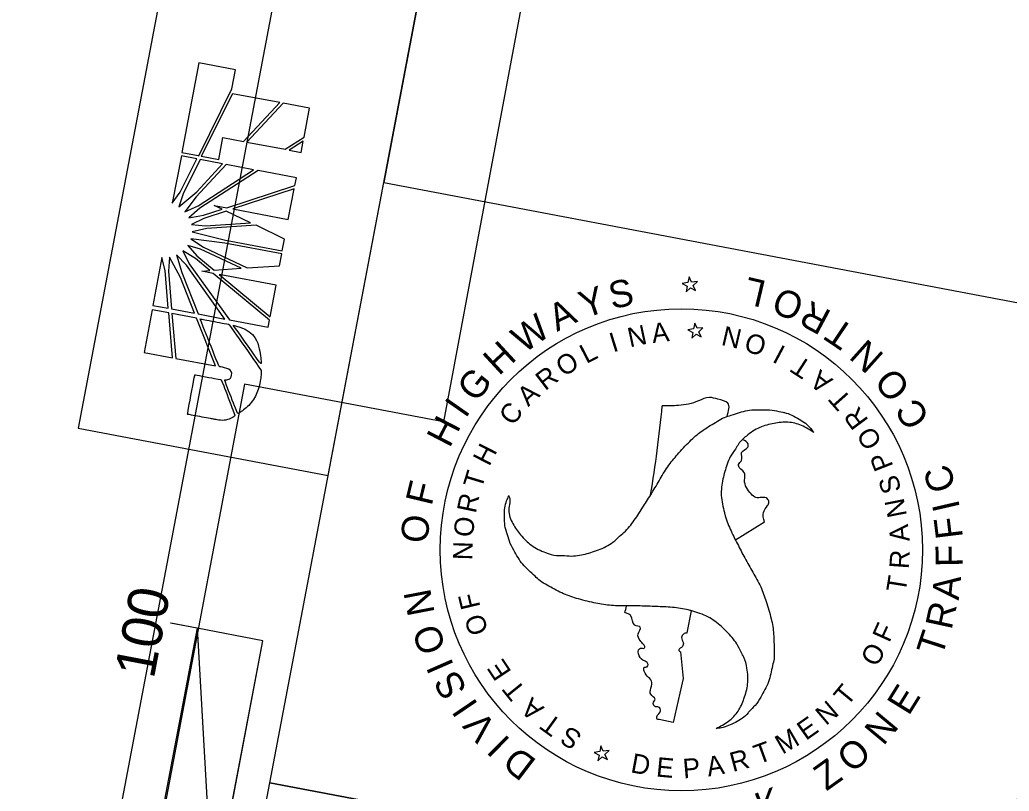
# Model space of a CAD drawing. Extents: x 1615680 to 1619687, y 899305 to 902270.
# Drawn here: x 1616793.9 to 1616978.5, y 900619.3 to 900763.2 of the extents above; entities that cross this region are included whole.
import ezdxf

# ---------------------------------------------------------------- set-up
doc = ezdxf.new("R2010")
doc.units = 0
for name, color, linetype in [('Default', 7, 'Continuous'), ('DEV PSS CELL', 7, 'Continuous'), ('PCB (Plan View)', 7, 'Continuous'), ('Prop Conc 4in Sidewalk', 7, 'Continuous'), ('Prop Mkg Solid Yel Skip RT Rpm 80ft', 7, 'Continuous'), ('Scratch_Level_3', 7, 'Continuous'), ('Scratch_Level_7', 7, 'Continuous'), ('Scratch_Level_8', 7, 'Continuous'), ('Stage 2', 7, 'Continuous')]:
    doc.layers.add(name, color=color, linetype=linetype)

msp = doc.modelspace()

# ---------------------------------------------------------------- linework, layer by layer
at = {"layer": 'Default'}
for p, q in [((1616827.31, 900755.17), (1616824.15, 900738.45)), ((1616834.16, 900753.88), (1616827.31, 900755.17)), ((1616833.49, 900750.32), (1616834.16, 900753.88)), ((1616827.31, 900737.85), (1616833.49, 900750.32)), ((1616833.63, 900749.42), (1616827.78, 900737.76)), ((1616842.41, 900747.76), (1616833.63, 900749.42)), ((1616835.63, 900740.51), (1616842.41, 900747.76)), ((1616843.03, 900747.65), (1616836.29, 900740.38)), ((1616847.97, 900746.71), (1616843.03, 900747.65)), ((1616846.95, 900741.32), (1616847.97, 900746.71)), ((1616831.04, 900737.15), (1616831.81, 900741.23)), ((1616831.81, 900741.23), (1616835.63, 900740.51)), ((1616843.4, 900739.04), (1616846.95, 900741.32)), ((1616846.8, 900740.53), (1616844.18, 900738.89)), ((1616846.41, 900738.47), (1616846.8, 900740.53)), ((1616836.29, 900740.38), (1616843.4, 900739.04)), ((1616844.18, 900738.89), (1616846.41, 900738.47)), ((1616824.07, 900737.82), (1616822.36, 900729.01)), ((1616823.84, 900731.04), (1616826.93, 900737.28)), ((1616826.93, 900737.28), (1616824.07, 900737.82)), ((1616824.15, 900738.45), (1616827.22, 900737.87)), ((1616827.54, 900737.17), (1616824.37, 900730.71)), ((1616827.22, 900737.87), (1616827.31, 900737.85)), ((1616831.74, 900736.32), (1616827.54, 900737.17)), ((1616827.78, 900737.76), (1616827.84, 900737.75)), ((1616827.84, 900737.75), (1616831.04, 900737.15)), ((1616832.45, 900736.19), (1616826.81, 900730.17)), ((1616826.95, 900731.13), (1616831.74, 900736.32)), ((1616827.18, 900728.51), (1616837.54, 900735.22)), ((1616838.37, 900735.07), (1616827.5, 900728.08)), ((1616837.54, 900735.22), (1616832.45, 900736.19)), ((1616845.51, 900733.72), (1616838.37, 900735.07)), ((1616845.25, 900732.31), (1616845.51, 900733.72)), ((1616832.52, 900728.14), (1616845.25, 900732.31)), ((1616845.08, 900731.66), (1616833.66, 900727.92)), ((1616844.01, 900725.97), (1616845.08, 900731.66)), ((1616822.36, 900729.01), (1616823.84, 900731.04)), ((1616823.59, 900728.31), (1616826.95, 900731.13)), ((1616824.37, 900730.71), (1616823.59, 900728.31)), ((1616826.81, 900730.17), (1616824.69, 900727.39)), ((1616824.69, 900727.39), (1616827.18, 900728.51)), ((1616827.5, 900728.08), (1616825.48, 900726.27)), ((1616828.21, 900726.76), (1616831.69, 900727.87)), ((1616831.69, 900727.87), (1616830.19, 900728.58)), ((1616830.19, 900728.58), (1616832.52, 900728.14)), ((1616833.66, 900727.92), (1616844.01, 900725.97)), ((1616825.48, 900726.27), (1616828.21, 900726.76)), ((1616828.28, 900726.16), (1616825.97, 900725.01)), ((1616832.4, 900727.52), (1616828.28, 900726.16)), ((1616836.99, 900725.33), (1616832.4, 900727.52)), ((1616825.97, 900725.01), (1616828.57, 900724.79)), ((1616828.83, 900724.24), (1616826.09, 900723.67)), ((1616828.57, 900724.79), (1616836.99, 900725.33)), ((1616837.99, 900724.87), (1616828.83, 900724.24)), ((1616843.31, 900722.28), (1616837.99, 900724.87)), ((1616832.18, 900721.51), (1616825.84, 900722.36)), ((1616825.84, 900722.36), (1616828.18, 900720.79)), ((1616826.09, 900723.67), (1616832.28, 900722.08)), ((1616832.28, 900722.08), (1616842.89, 900720.07)), ((1616842.89, 900720.07), (1616843.31, 900722.28)), ((1616825.24, 900721.11), (1616826.96, 900719.15)), ((1616827.65, 900720.42), (1616825.24, 900721.11)), ((1616835.2, 900716.86), (1616827.65, 900720.42)), ((1616828.18, 900720.79), (1616836.35, 900716.92)), ((1616842.79, 900719.51), (1616832.18, 900721.51)), ((1616820.45, 900718.87), (1616818.76, 900709.92)), ((1616821.03, 900716.4), (1616820.45, 900718.87)), ((1616821.82, 900718.94), (1616821.64, 900716.28)), ((1616823.88, 900715.14), (1616821.82, 900718.94)), ((1616825.04, 900717.42), (1616823.18, 900719.36)), ((1616823.18, 900719.36), (1616824.14, 900716.04)), ((1616824.31, 900720.1), (1616825.54, 900717.68)), ((1616826.67, 900718.65), (1616824.31, 900720.1)), ((1616829.39, 900716.41), (1616826.67, 900718.65)), ((1616826.96, 900719.15), (1616830.18, 900716.49)), ((1616842.37, 900717.33), (1616842.79, 900719.51)), ((1616832.19, 900707.38), (1616825.04, 900717.42)), ((1616825.54, 900717.68), (1616833.03, 900707.22)), ((1616830.18, 900716.49), (1616835.2, 900716.86)), ((1616836.35, 900716.92), (1616842.37, 900717.33)), ((1616821.61, 900709.38), (1616821.03, 900716.4)), ((1616821.64, 900716.28), (1616822.22, 900709.27)), ((1616826.53, 900708.45), (1616823.88, 900715.14)), ((1616824.14, 900716.04), (1616827.22, 900708.32)), ((1616827.87, 900716.29), (1616829.39, 900716.41)), ((1616829.97, 900715.89), (1616827.87, 900716.29)), ((1616840.5, 900707.17), (1616829.97, 900715.89)), ((1616841.73, 900713.72), (1616831.12, 900715.68)), ((1616831.12, 900715.68), (1616840.61, 900707.79)), ((1616840.61, 900707.79), (1616841.73, 900713.72)), ((1616818.76, 900709.92), (1616821.61, 900709.38)), ((1616822.22, 900709.27), (1616826.53, 900708.45)), ((1616818.64, 900709.09), (1616817.14, 900701.13)), ((1616821.71, 900708.51), (1616818.64, 900709.09)), ((1616822.41, 900700.13), (1616821.71, 900708.51)), ((1616826.9, 900707.53), (1616822.29, 900708.4)), ((1616822.29, 900708.4), (1616823.02, 900700.02)), ((1616830.44, 900698.62), (1616826.9, 900707.53)), ((1616827.22, 900708.32), (1616832.19, 900707.38)), ((1616833.03, 900707.22), (1616840.25, 900705.86)), ((1616840.25, 900705.86), (1616840.5, 900707.17)), ((1616817.14, 900701.13), (1616822.41, 900700.13)), ((1616823.02, 900700.02), (1616830.44, 900698.62))]:
    msp.add_line(p, q, dxfattribs=at)
for points in [[(1616827.78, 900737.76), (1616827.84, 900737.75), (1616831.04, 900737.15), (1616831.81, 900741.23), (1616835.63, 900740.51), (1616842.41, 900747.76), (1616833.63, 900749.42), (1616827.78, 900737.76)], [(1616836.29, 900740.38), (1616843.4, 900739.04), (1616846.95, 900741.32), (1616847.97, 900746.71), (1616843.03, 900747.65), (1616836.29, 900740.38), (1616836.29, 900740.38)], [(1616846.41, 900738.47), (1616846.41, 900738.47), (1616846.8, 900740.53), (1616844.18, 900738.89), (1616846.41, 900738.47)], [(1616823.84, 900731.04), (1616826.93, 900737.28), (1616824.07, 900737.82), (1616822.36, 900729.01), (1616823.84, 900731.04)], [(1616823.59, 900728.31), (1616826.95, 900731.13), (1616831.74, 900736.32), (1616827.54, 900737.17), (1616824.37, 900730.71), (1616823.59, 900728.31)], [(1616824.69, 900727.39), (1616827.18, 900728.51), (1616837.54, 900735.22), (1616832.45, 900736.19), (1616826.81, 900730.17), (1616824.69, 900727.39)], [(1616825.48, 900726.27), (1616828.21, 900726.76), (1616831.69, 900727.87), (1616830.19, 900728.58), (1616832.52, 900728.14), (1616845.25, 900732.31), (1616845.51, 900733.72), (1616838.37, 900735.07), (1616827.5, 900728.08), (1616825.48, 900726.27)], [(1616844.01, 900725.97), (1616845.08, 900731.66), (1616833.66, 900727.92), (1616844.01, 900725.97)], [(1616825.97, 900725.01), (1616828.57, 900724.79), (1616836.99, 900725.33), (1616832.4, 900727.52), (1616828.28, 900726.16), (1616825.97, 900725.01)], [(1616826.09, 900723.67), (1616832.28, 900722.08), (1616842.89, 900720.07), (1616843.31, 900722.28), (1616837.99, 900724.87), (1616828.83, 900724.24), (1616826.09, 900723.67)], [(1616828.18, 900720.79), (1616836.35, 900716.92), (1616842.37, 900717.33), (1616842.79, 900719.51), (1616832.18, 900721.51), (1616825.84, 900722.36), (1616828.18, 900720.79)], [(1616825.24, 900721.11), (1616826.96, 900719.15), (1616830.18, 900716.49), (1616835.2, 900716.86), (1616827.65, 900720.42), (1616825.24, 900721.11)], [(1616821.03, 900716.4), (1616820.45, 900718.87), (1616818.76, 900709.92), (1616821.61, 900709.38), (1616821.03, 900716.4)], [(1616822.22, 900709.27), (1616826.53, 900708.45), (1616823.88, 900715.14), (1616821.82, 900718.94), (1616821.64, 900716.28), (1616822.22, 900709.27)], [(1616827.22, 900708.32), (1616832.19, 900707.38), (1616825.04, 900717.42), (1616823.18, 900719.36), (1616824.14, 900716.04), (1616827.22, 900708.32)], [(1616824.31, 900720.1), (1616825.54, 900717.68), (1616833.03, 900707.22), (1616840.25, 900705.86), (1616840.5, 900707.17), (1616829.97, 900715.89), (1616827.87, 900716.29), (1616829.39, 900716.41), (1616826.67, 900718.65), (1616824.31, 900720.1)], [(1616840.61, 900707.79), (1616841.73, 900713.72), (1616831.12, 900715.68), (1616840.61, 900707.79)], [(1616822.41, 900700.13), (1616821.71, 900708.51), (1616818.64, 900709.09), (1616817.14, 900701.13), (1616822.41, 900700.13)], [(1616830.44, 900698.62), (1616826.9, 900707.53), (1616822.29, 900708.4), (1616823.02, 900700.02), (1616830.44, 900698.62)]]:
    msp.add_lwpolyline(points, dxfattribs=at)
for points in [[(1616833.44, 900696.87), (1616833.35, 900696.4), (1616833.01, 900696.04), (1616832.1, 900696.03), (1616832.1, 900696.03), (1616834.55, 900689.66), (1616834.55, 900689.66), (1616836.73, 900691.07), (1616838.37, 900693.67), (1616838.81, 900696.04), (1616838.93, 900696.66), (1616838.97, 900697.14), (1616838.96, 900697.82), (1616838.96, 900697.82), (1616832.91, 900706.39), (1616832.91, 900706.39), (1616832.91, 900706.39), (1616827.55, 900707.4), (1616827.55, 900707.4), (1616827.55, 900707.4), (1616831.11, 900698.49), (1616831.11, 900698.49), (1616833.11, 900698.11), (1616833.56, 900697.52), (1616833.44, 900696.87)], [(1616833.44, 900696.87), (1616833.35, 900696.4), (1616833.01, 900696.04), (1616832.1, 900696.03), (1616832.1, 900696.03), (1616834.55, 900689.66), (1616834.55, 900689.66), (1616836.73, 900691.07), (1616838.37, 900693.67), (1616838.81, 900696.04), (1616838.93, 900696.66), (1616838.97, 900697.14), (1616838.96, 900697.82), (1616838.96, 900697.82), (1616832.91, 900706.39), (1616832.91, 900706.39), (1616832.91, 900706.39), (1616827.55, 900707.4), (1616827.55, 900707.4), (1616827.55, 900707.4), (1616831.11, 900698.49), (1616831.11, 900698.49), (1616833.11, 900698.11), (1616833.56, 900697.52), (1616833.44, 900696.87)], [(1616833.75, 900706.23), (1616833.75, 900706.23), (1616838.97, 900698.83), (1616838.97, 900698.83), (1616838.8, 900702), (1616837.36, 900705.4), (1616833.75, 900706.23)], [(1616833.75, 900706.23), (1616833.75, 900706.23), (1616838.97, 900698.83), (1616838.97, 900698.83), (1616838.8, 900702), (1616837.36, 900705.4), (1616833.75, 900706.23)], [(1616826.59, 900696.98), (1616826.59, 900696.98), (1616825.2, 900689.61), (1616825.2, 900689.61), (1616825.2, 900689.61), (1616829.81, 900688.74), (1616829.81, 900688.74), (1616829.81, 900688.74), (1616830.29, 900688.65), (1616830.29, 900688.65), (1616831.74, 900688.38), (1616832.97, 900688.64), (1616834.09, 900689.29), (1616834.09, 900689.29), (1616831.55, 900696.04), (1616831.46, 900696.06), (1616831.46, 900696.06), (1616826.59, 900696.98), (1616826.59, 900696.98)], [(1616826.59, 900696.98), (1616826.59, 900696.98), (1616825.2, 900689.61), (1616825.2, 900689.61), (1616825.2, 900689.61), (1616829.81, 900688.74), (1616829.81, 900688.74), (1616829.81, 900688.74), (1616830.29, 900688.65), (1616830.29, 900688.65), (1616831.74, 900688.38), (1616832.97, 900688.64), (1616834.09, 900689.29), (1616834.09, 900689.29), (1616831.55, 900696.04), (1616831.46, 900696.06), (1616831.46, 900696.06), (1616826.59, 900696.98), (1616826.59, 900696.98)]]:
    msp.add_open_spline(points, degree=3, dxfattribs=at)
at = {"layer": 'DEV PSS CELL'}
msp.add_lwpolyline([(1616859.19, 900973.59), (1616804.79, 900687.04), (1616851.47, 900678.18), (1616905.88, 900964.73)], close=True, dxfattribs=at)
at = {"layer": 'PCB (Plan View)'}
for p, q in [((1616826.98, 900649.69), (1616822.07, 900650.62)), ((1616826.98, 900649.69), (1616799.02, 900502.32)), ((1616839.28, 900647.36), (1616826.98, 900649.69)), ((1616811.3, 900499.99), (1616839.28, 900647.36))]:
    msp.add_line(p, q, dxfattribs=at)
msp.add_lwpolyline([(1616826.98, 900649.69), (1616829.94, 900598.24), (1616839.28, 900647.36)], close=True, dxfattribs=at)
at = {"layer": 'Prop Conc 4in Sidewalk'}
msp.add_lwpolyline([(1616176.29, 901060.7), (1616848.46, 900914.27), (1616896.28, 900812.91), (1616872.94, 900688.21), (1616835.87, 900695.21), (1616753.94, 900262.18), (1616898.09, 900233.43), (1616734.79, 899562.1), (1616202.98, 899609.43), (1616198.71, 899647.14), (1615822.69, 899825.07), (1616054.34, 901080.76)], close=True, dxfattribs=at)
at = {"layer": 'Prop Mkg Solid Yel Skip RT Rpm 80ft'}
msp.add_circle((1616917.34, 900664.32), 44.97, dxfattribs=at)
at = {"layer": 'Scratch_Level_3'}
for p, q in [((1616918.77, 900715.25), (1616918.56, 900714.19)), ((1616919.23, 900714.26), (1616918.77, 900715.25)), ((1616918.56, 900714.19), (1616917.51, 900714.02)), ((1616917.51, 900714.02), (1616918.44, 900713.51)), ((1616918.44, 900713.51), (1616918.23, 900712.45)), ((1616918.23, 900712.45), (1616919.03, 900713.2)), ((1616919.03, 900713.2), (1616920, 900712.69)), ((1616920.32, 900714.39), (1616919.23, 900714.26)), ((1616919.52, 900713.63), (1616920.32, 900714.39)), ((1616920, 900712.69), (1616919.52, 900713.63)), ((1616919.62, 900705.56), (1616918.56, 900705.39)), ((1616919.82, 900706.62), (1616919.62, 900705.56)), ((1616920.28, 900705.64), (1616919.82, 900706.62)), ((1616921.37, 900705.76), (1616920.28, 900705.64)), ((1616920.58, 900705.01), (1616921.37, 900705.76)), ((1616918.56, 900705.39), (1616919.49, 900704.89)), ((1616919.49, 900704.89), (1616919.29, 900703.83)), ((1616919.29, 900703.83), (1616920.08, 900704.57)), ((1616920.08, 900704.57), (1616921.05, 900704.06)), ((1616921.05, 900704.06), (1616920.58, 900705.01)), ((1616927.43, 900666.17), (1616932.82, 900669.53)), ((1616918.41, 900648.8), (1616919.23, 900652.93)), ((1616917.17, 900645.27), (1616917.66, 900640.28)), ((1616917.66, 900640.28), (1616915.79, 900632.1)), ((1616915.79, 900632.1), (1616913.19, 900632.68)), ((1616902.1, 900626.67), (1616901.05, 900626.51)), ((1616901.05, 900626.51), (1616901.98, 900626)), ((1616902.31, 900627.74), (1616902.1, 900626.67)), ((1616902.77, 900626.75), (1616902.31, 900627.74)), ((1616903.86, 900626.87), (1616902.77, 900626.75)), ((1616903.06, 900626.12), (1616903.86, 900626.87)), ((1616903.54, 900625.18), (1616903.06, 900626.12)), ((1616901.98, 900626), (1616901.78, 900624.94)), ((1616901.78, 900624.94), (1616902.57, 900625.69)), ((1616902.57, 900625.69), (1616903.54, 900625.18))]:
    msp.add_line(p, q, dxfattribs=at)
for start, end in [(350.4529, 354.5729), (344.9279, 345.2256)]:
    msp.add_arc((1616681.63, 900713.24), 233.19, start, end, dxfattribs=at)
for points in [[(1616925.85, 900689.2), (1616926.01, 900691.68), (1616924.16, 900692.4), (1616922.56, 900692.74), (1616920.51, 900692.09), (1616916.81, 900691.24), (1616913.77, 900691.18)], [(1616885.09, 900674.44), (1616885.15, 900674.35), (1616885.14, 900671.73), (1616885.9, 900669.21), (1616887.35, 900667.1), (1616889.36, 900665.16), (1616892, 900663.79), (1616894.06, 900663.26), (1616895.09, 900663.25), (1616896.88, 900663.16), (1616898.33, 900663.29), (1616901.12, 900664.05), (1616903.92, 900665.29), (1616906.42, 900667.39), (1616906.62, 900667.57), (1616908.56, 900669.82), (1616910.25, 900672.43), (1616911.82, 900674.91), (1616913.38, 900677.54), (1616915.02, 900680.12), (1616916.87, 900682.4), (1616919.19, 900684.83), (1616921.43, 900686.67), (1616924.06, 900688.3), (1616925.37, 900689.03), (1616926.65, 900689.42), (1616929.69, 900690.32), (1616932.83, 900690.43), (1616934.72, 900690.32), (1616936.29, 900689.97), (1616936.55, 900689.92), (1616939.3, 900688.71), (1616941.48, 900686.96), (1616942.02, 900686.2)], [(1616942.02, 900686.2), (1616939.76, 900687.51), (1616937.22, 900688.12), (1616934.64, 900687.9), (1616931.95, 900687.13), (1616929.47, 900685.55), (1616927.98, 900684.03), (1616927.45, 900683.12), (1616926.46, 900681.67), (1616925.87, 900680.28), (1616925.1, 900677.53), (1616924.79, 900674.45), (1616925.36, 900671.25), (1616925.42, 900670.99), (1616926.44, 900668.18), (1616927.8, 900665.43), (1616929.16, 900662.79), (1616930.68, 900660.13), (1616932.13, 900657.42), (1616933.14, 900654.69), (1616934.09, 900651.45), (1616934.55, 900648.6), (1616934.65, 900645.52), (1616934.64, 900643.99), (1616934.34, 900642.71), (1616933.59, 900639.66), (1616932.13, 900636.85), (1616931.1, 900635.29), (1616929.97, 900634.12), (1616929.8, 900633.9), (1616927.41, 900632.12), (1616924.81, 900631.11), (1616923.83, 900630.99)], [(1616932.82, 900669.53), (1616932.64, 900671.29), (1616933.43, 900672.58), (1616933.66, 900673.23), (1616933.35, 900673.86), (1616931.24, 900674.09), (1616930.36, 900674.75), (1616929.12, 900677.31), (1616929.08, 900678.76), (1616927.99, 900680.03), (1616928.1, 900680.44), (1616928.58, 900681.01), (1616928.57, 900682.48), (1616929.71, 900683.44), (1616929.78, 900684.12), (1616928.83, 900684.85)], [(1616923.83, 900630.99), (1616926.14, 900632.33), (1616927.91, 900634.21), (1616929.01, 900636.54), (1616929.7, 900639.28), (1616929.57, 900642.22), (1616928.98, 900644.28), (1616928.5, 900645.19), (1616927.68, 900646.76), (1616926.81, 900647.94), (1616924.8, 900650.02), (1616922.29, 900651.8), (1616919.26, 900652.93), (1616919, 900653), (1616916.04, 900653.54), (1616912.98, 900653.71), (1616910.03, 900653.83), (1616906.95, 900653.87), (1616903.91, 900653.96), (1616901.02, 900654.45), (1616897.76, 900655.26), (1616895.03, 900656.27), (1616892.3, 900657.74), (1616891.02, 900658.51), (1616890.04, 900659.4), (1616887.76, 900661.61), (1616886.08, 900664.25), (1616885.25, 900665.94), (1616884.78, 900667.48), (1616884.69, 900667.74), (1616884.32, 900670.71), (1616884.74, 900673.47), (1616885.15, 900674.35)], [(1616913.19, 900632.68), (1616912.93, 900632.64), (1616912.74, 900633.14), (1616913.47, 900634.27), (1616913.06, 900634.98), (1616912.52, 900635.05), (1616912.09, 900635.65), (1616912.42, 900636.45), (1616911.61, 900637.38), (1616911.55, 900638.11), (1616911.83, 900639.58), (1616910.41, 900641.66), (1616910.44, 900642.4), (1616910.95, 900642.51), (1616911.12, 900642.94), (1616909.82, 900643.99), (1616909.66, 900644.22), (1616909.36, 900645.66), (1616909.71, 900645.97), (1616910.37, 900645.96), (1616910.51, 900646.13), (1616910.29, 900646.63), (1616909.63, 900647.39), (1616909.26, 900648.61), (1616909.67, 900649.86), (1616908.65, 900650.28), (1616907.94, 900651.97), (1616907.39, 900652.39), (1616906.79, 900652.59)], [(1616918.41, 900648.8), (1616917.71, 900648.59), (1616917.39, 900647.96), (1616917.69, 900646.95), (1616917.54, 900646.29), (1616916.84, 900645.65), (1616917.17, 900645.27)]]:
    msp.add_spline(points, degree=3, dxfattribs=at)
at = {"layer": 'Scratch_Level_7'}
for points in [[(1616905.88, 900964.73), (1616861.86, 900732.87), (1616996.95, 900707.23), (1617040.97, 900939.08)], [(1616840.59, 900620.87), (1616861.86, 900732.87), (1616996.95, 900707.23), (1616975.68, 900595.22)], [(1616803.28, 900424.35), (1616840.59, 900620.87), (1616975.68, 900595.22), (1616938.37, 900398.7)]]:
    msp.add_lwpolyline(points, close=True, dxfattribs=at)
at = {"layer": 'Scratch_Level_8'}
msp.add_lwpolyline([(1616054.34, 901080.76), (1615793.19, 899705.33), (1616726.52, 899528.12), (1616890.46, 900391.55), (1616774.26, 900413.61), (1616871.48, 900925.61)], close=True, dxfattribs=at)
at = {"layer": 'Stage 2'}
msp.add_line((1616826.99, 900649.7), (1616822.06, 900650.64), dxfattribs=at)

# ---------------------------------------------------------------- texts
at = {"layer": 'PCB (Plan View)'}
msp.add_text('100', height=7.5, rotation=79.2541, dxfattribs=at).set_placement((1616818.91, 900640.06))
at = {"layer": 'Prop Mkg Solid Yel Skip RT Rpm 80ft'}
for s, height, rotation, p in [('L', 5.04, 166.6784, (1616933.41, 900714.4)), ('O', 5.04, 158.239, (1616940.59, 900711.5)), ('R', 5.04, 152.0012, (1616945.58, 900708.69)), ('T', 5.04, 146.1304, (1616949.97, 900705.57)), ('N', 5.04, 138.1413, (1616955.38, 900700.64)), ('O', 5.04, 129.702, (1616960.3, 900694.66)), ('C', 5.04, 122.3301, (1616963.84, 900688.9)), ('C', 5.04, 107.2527, (1616968.63, 900675.95)), ('T', 3.63, 73.0378, (1616880.06, 900675.5)), ('I', 5.04, 102.9996, (1616969.35, 900672.12)), ('F', 5.04, 97.012, (1616969.88, 900666.65)), ('F', 5.04, 91.0244, (1616969.84, 900661.16)), ('A', 5.04, 84.0528, (1616969.07, 900654.81)), ('R', 5.04, 77.815, (1616967.73, 900649.24)), ('T', 5.04, 71.9442, (1616965.92, 900644.17)), ('E', 5.04, 58.201, (1616959.74, 900633.2)), ('N', 5.04, 50.212, (1616955.01, 900627.61)), ('O', 5.04, 41.7727, (1616949.21, 900622.48)), ('Z', 5.04, 35.4181, (1616944.38, 900619.21)), ('K', 5.04, 21.0412, (1616932.34, 900613.91))]:
    msp.add_text(s, height=height, rotation=rotation, dxfattribs=at).set_placement(p)
at = {"layer": 'Scratch_Level_3'}
for s, height, rotation, p in [('S', 5.04, 12.4743, (1616904.4, 900709.18)), ('Y', 5.04, 18.9977, (1616899.33, 900707.45)), ('A', 5.04, 26.0256, (1616894.13, 900704.96)), ('W', 5.04, 35.0626, (1616887.96, 900700.86)), ('N', 3.63, 12.1007, (1616907.73, 900702.07)), ('A', 3.63, 7.0227, (1616912.01, 900702.88)), ('N', 3.63, 166.9823, (1616928.85, 900705.33)), ('I', 3.63, 17.1788, (1616904.59, 900701.12)), ('O', 3.63, 162.1763, (1616933.52, 900703.81)), ('H', 5.04, 42.7126, (1616883.29, 900696.66)), ('L', 3.63, 27.335, (1616899.6, 900698.96)), ('I', 3.63, 152.0201, (1616937.01, 900702.05)), ('O', 3.63, 32.4131, (1616895.39, 900696.49)), ('T', 3.63, 146.942, (1616941.93, 900699.08)), ('R', 3.63, 37.4912, (1616891.93, 900693.88)), ('A', 3.63, 141.8639, (1616945.78, 900696.08)), ('G', 5.04, 50.7661, (1616879.02, 900691.62)), ('A', 3.63, 42.5693, (1616888.77, 900690.92)), ('I', 5.04, 55.0534, (1616877.05, 900688.7)), ('T', 3.63, 131.7077, (1616949.3, 900692.41)), ('C', 3.63, 52.7254, (1616885.92, 900687.29)), ('R', 3.63, 126.6297, (1616952.37, 900688.51)), ('H', 5.04, 62.7034, (1616874.1, 900683.16)), ('O', 3.63, 121.5516, (1616954.91, 900684.44)), ('H', 3.63, 62.8816, (1616881.51, 900679.75)), ('P', 3.63, 111.3954, (1616956.93, 900679.91)), ('S', 3.63, 106.3173, (1616958.42, 900675.42)), ('F', 5.04, 76.5069, (1616870.74, 900672.37)), ('R', 3.63, 78.1158, (1616878.97, 900670.99)), ('N', 3.63, 101.2392, (1616959.44, 900670.73)), ('O', 5.04, 85.0143, (1616869.99, 900665.43)), ('O', 3.63, 83.1939, (1616878.41, 900666.54)), ('A', 3.63, 96.1611, (1616959.95, 900665.98)), ('N', 3.63, 88.272, (1616878.34, 900662.34)), ('R', 3.63, 86.005, (1616959.73, 900660.67)), ('T', 3.63, 80.9269, (1616959.13, 900656.22)), ('N', 5.04, 100.8354, (1616871.34, 900652.55)), ('F', 3.63, 103.5063, (1616879.87, 900653.68)), ('O', 3.63, 108.5844, (1616881.39, 900649.11)), ('F', 3.63, 65.6926, (1616956.13, 900646.85)), ('O', 5.04, 109.3428, (1616873.51, 900645.92)), ('O', 3.63, 60.6146, (1616953.76, 900642.29)), ('I', 5.04, 113.6302, (1616874.97, 900642.72)), ('E', 3.63, 123.8186, (1616885.75, 900641.55)), ('S', 5.04, 119.8342, (1616877.51, 900638.3)), ('T', 3.63, 128.8967, (1616888.47, 900638.12)), ('T', 3.63, 50.4584, (1616948.28, 900634.98)), ('I', 5.04, 124.1215, (1616879.53, 900635.42)), ('A', 3.63, 139.0529, (1616891.9, 900634.86)), ('N', 3.63, 40.3022, (1616944.31, 900631.41)), ('V', 5.04, 130.83, (1616883.1, 900631.23)), ('T', 3.63, 144.1309, (1616895.27, 900632.25)), ('E', 3.63, 35.2241, (1616940.57, 900628.64)), ('S', 3.63, 149.209, (1616899.04, 900629.92)), ('M', 3.63, 30.146, (1616936.19, 900626.07)), ('I', 5.04, 135.1173, (1616885.64, 900628.79)), ('T', 3.63, 19.9899, (1616931.68, 900624.26)), ('D', 5.04, 142.7084, (1616890.54, 900624.96)), ('D', 3.63, 349.5214, (1616907.73, 900622.83)), ('R', 3.63, 14.9118, (1616926.93, 900622.84)), ('E', 3.63, 354.5995, (1616912.53, 900622.04)), ('P', 3.63, 4.7556, (1616917.75, 900621.66)), ('A', 3.63, 9.8337, (1616922.36, 900622.01))]:
    msp.add_text(s, height=height, rotation=rotation, dxfattribs=at).set_placement(p)

doc.saveas('drawing.dxf')
